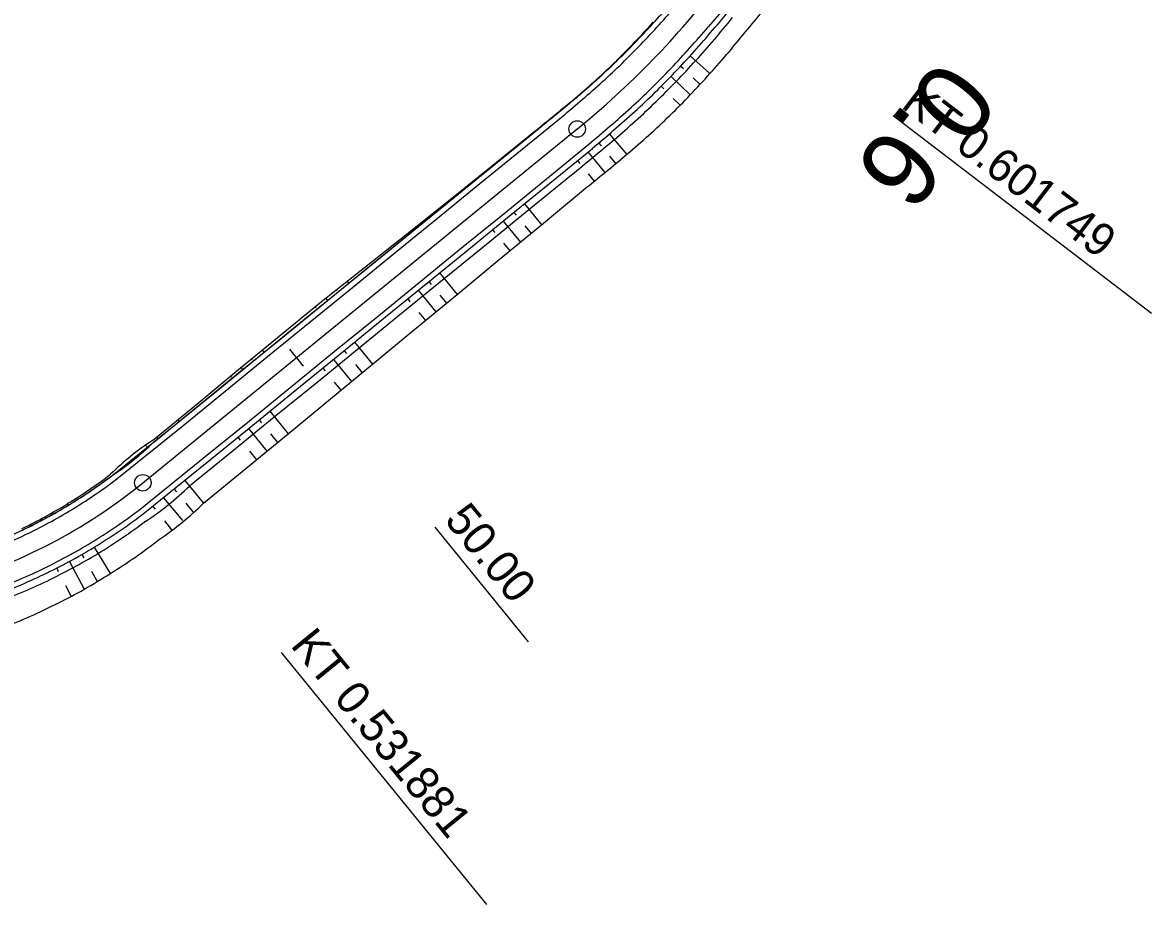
# Model space of a CAD drawing. Extents: x -481656 to -478728, y -1113199 to -1110710.
# Drawn here: x -479536.3 to -479433.2, y -1111452.2 to -1111371.6 of the extents above; entities that cross this region are included whole.
import ezdxf

# ---------------------------------------------------------------- set-up
doc = ezdxf.new("R2010")
doc.units = 0
for name, color, linetype in [('C5_HATCH_SLOPE_L', 7, 'Continuous'), ('C5_HATCH_SLOPE_R', 7, 'Continuous'), ('C5_HECTOMETRY', 7, 'Continuous'), ('C5_HLBODY', 7, 'Continuous'), ('C5_HRANA_TELESO', 7, 'Continuous'), ('C5_KORUNA', 7, 'Continuous'), ('C5_OSA', 7, 'Continuous'), ('C5_PRIKOP', 7, 'Continuous'), ('C5_STANICENI', 7, 'Continuous'), ('C5_ZPEVKRAJ', 7, 'Continuous')]:
    doc.layers.add(name, color=color, linetype=linetype)

msp = doc.modelspace()

# ---------------------------------------------------------------- linework, layer by layer
at = {"layer": 'C5_HATCH_SLOPE_L'}
for p, q in [((-479479.15, -1111372.09), (-479479.17, -1111372.07)), ((-479479.13, -1111372.11), (-479479.13, -1111372.11)), ((-479483.43, -1111376.4), (-479483.45, -1111376.38)), ((-479484.34, -1111377.2), (-479484.35, -1111377.19)), ((-479484.33, -1111377.22), (-479484.33, -1111377.22)), ((-479486.18, -1111378.79), (-479486.18, -1111378.78)), ((-479486.16, -1111378.81), (-479486.16, -1111378.81)), ((-479485.24, -1111378.02), (-479485.26, -1111378)), ((-479490.97, -1111382.75), (-479491, -1111382.71)), ((-479491.96, -1111383.51), (-479491.97, -1111383.5)), ((-479491.94, -1111383.54), (-479491.95, -1111383.53)), ((-479493.9, -1111385.09), (-479493.91, -1111385.08)), ((-479493.88, -1111385.12), (-479493.88, -1111385.11)), ((-479492.91, -1111384.33), (-479492.94, -1111384.29)), ((-479498.73, -1111389.06), (-479498.79, -1111388.98)), ((-479499.74, -1111389.8), (-479499.77, -1111389.76)), ((-479499.69, -1111389.85), (-479499.7, -1111389.85)), ((-479501.69, -1111391.37), (-479501.73, -1111391.31)), ((-479500.66, -1111390.64), (-479500.75, -1111390.53)), ((-479501.63, -1111391.43), (-479501.64, -1111391.43)), ((-479506.48, -1111395.38), (-479506.63, -1111395.19)), ((-479507.53, -1111396.07), (-479507.6, -1111395.98)), ((-479507.45, -1111396.17), (-479507.45, -1111396.17)), ((-479508.41, -1111396.96), (-479508.58, -1111396.76)), ((-479509.47, -1111397.64), (-479509.55, -1111397.54)), ((-479509.38, -1111397.75), (-479509.39, -1111397.75)), ((-479514.23, -1111401.7), (-479514.39, -1111401.5)), ((-479515.28, -1111402.39), (-479515.36, -1111402.29)), ((-479515.2, -1111402.49), (-479515.2, -1111402.49)), ((-479516.17, -1111403.28), (-479516.33, -1111403.08)), ((-479517.22, -1111403.97), (-479517.29, -1111403.88)), ((-479517.14, -1111404.07), (-479517.14, -1111404.06)), ((-479523.02, -1111408.72), (-479523.08, -1111408.65)), ((-479522.95, -1111408.81), (-479522.95, -1111408.8)), ((-479521.98, -1111408.02), (-479522.11, -1111407.85)), ((-479523.92, -1111409.6), (-479524.05, -1111409.44)), ((-479524.95, -1111410.3), (-479525.01, -1111410.23)), ((-479524.89, -1111410.39), (-479524.89, -1111410.38)), ((-479532.09, -1111415.68), (-479532.18, -1111415.53)), ((-479534.16, -1111416.87), (-479534.24, -1111416.72)), ((-479533.16, -1111416.21), (-479533.2, -1111416.14)), ((-479533.12, -1111416.28), (-479533.12, -1111416.28)), ((-479535.26, -1111417.35), (-479535.29, -1111417.28)), ((-479535.22, -1111417.42), (-479535.22, -1111417.42))]:
    msp.add_line(p, q, dxfattribs=at)
at = {"layer": 'C5_HATCH_SLOPE_R'}
for p, q in [((-479475.31, -1111374.61), (-479473.52, -1111376.24)), ((-479476.18, -1111375.55), (-479475.94, -1111375.78)), ((-479477.07, -1111376.48), (-479475.31, -1111378.18)), ((-479475.05, -1111376.61), (-479474.41, -1111377.22)), ((-479477.97, -1111377.4), (-479477.73, -1111377.63)), ((-479476.87, -1111378.5), (-479476.24, -1111379.13)), ((-479482.68, -1111381.77), (-479481.1, -1111383.62)), ((-479483.67, -1111382.59), (-479483.45, -1111382.85)), ((-479484.65, -1111383.4), (-479483.11, -1111385.28)), ((-479482.68, -1111383.79), (-479482.11, -1111384.47)), ((-479485.62, -1111384.19), (-479485.41, -1111384.45)), ((-479484.64, -1111385.39), (-479484.08, -1111386.07)), ((-479490.46, -1111388.14), (-479488.89, -1111390.07)), ((-479491.43, -1111388.93), (-479491.22, -1111389.18)), ((-479492.4, -1111389.72), (-479490.82, -1111391.65)), ((-479490.43, -1111390.15), (-479489.85, -1111390.86)), ((-479493.37, -1111390.51), (-479493.16, -1111390.76)), ((-479492.37, -1111391.73), (-479491.79, -1111392.44)), ((-479499.18, -1111395.24), (-479498.97, -1111395.5)), ((-479498.21, -1111394.45), (-479496.61, -1111396.42)), ((-479500.15, -1111396.03), (-479498.54, -1111398.01)), ((-479498.17, -1111396.49), (-479497.57, -1111397.22)), ((-479501.12, -1111396.82), (-479500.91, -1111397.08)), ((-479500.1, -1111398.07), (-479499.5, -1111398.81)), ((-479506.93, -1111401.56), (-479506.72, -1111401.82)), ((-479505.97, -1111400.77), (-479504.32, -1111402.79)), ((-479507.9, -1111402.35), (-479506.25, -1111404.38)), ((-479508.87, -1111403.14), (-479508.66, -1111403.4)), ((-479505.9, -1111402.83), (-479505.28, -1111403.58)), ((-479507.83, -1111404.42), (-479507.21, -1111405.18)), ((-479513.72, -1111407.09), (-479512.04, -1111409.15)), ((-479515.66, -1111408.67), (-479513.97, -1111410.74)), ((-479514.69, -1111407.88), (-479514.48, -1111408.14)), ((-479516.62, -1111409.46), (-479516.41, -1111409.72)), ((-479513.64, -1111409.17), (-479513, -1111409.94)), ((-479515.57, -1111410.75), (-479514.94, -1111411.53)), ((-479521.47, -1111413.41), (-479519.77, -1111415.5)), ((-479523.41, -1111414.99), (-479521.69, -1111417.09)), ((-479522.44, -1111414.2), (-479522.23, -1111414.45)), ((-479524.4, -1111415.79), (-479524.19, -1111416.05)), ((-479521.37, -1111415.5), (-479520.73, -1111416.29)), ((-479523.34, -1111417.12), (-479522.7, -1111417.93)), ((-479530.88, -1111420.19), (-479530.71, -1111420.48)), ((-479529.76, -1111419.52), (-479528.29, -1111421.93)), ((-479532.02, -1111420.82), (-479530.66, -1111423.34)), ((-479533.18, -1111421.43), (-479533.03, -1111421.73)), ((-479530.01, -1111421.71), (-479529.47, -1111422.65)), ((-479532.37, -1111423.02), (-479531.86, -1111424.01))]:
    msp.add_line(p, q, dxfattribs=at)
at = {"layer": 'C5_HLBODY'}
for p, q in [((-479456.77, -1111380.07), (-479433.19, -1111398.12)), ((-479512.67, -1111429.14), (-479493.91, -1111452.16))]:
    msp.add_line(p, q, dxfattribs=at)
for centre in [(-479485.64, -1111381.3), (-479525.31, -1111413.63)]:
    msp.add_circle(centre, 0.75, dxfattribs=at)
at = {"layer": 'C5_HRANA_TELESO'}
for p, q in [((-479493.34, -1111384.61), (-479489.46, -1111381.46)), ((-479497.23, -1111387.75), (-479493.34, -1111384.61)), ((-479488.89, -1111390.07), (-479485.05, -1111386.86)), ((-479501.15, -1111390.85), (-479497.23, -1111387.75)), ((-479492.76, -1111393.23), (-479488.89, -1111390.07)), ((-479505.07, -1111393.96), (-479501.15, -1111390.85)), ((-479496.61, -1111396.42), (-479492.76, -1111393.23)), ((-479508.99, -1111397.06), (-479505.07, -1111393.96)), ((-479500.47, -1111399.6), (-479496.61, -1111396.42)), ((-479512.85, -1111400.24), (-479508.99, -1111397.06)), ((-479516.72, -1111403.41), (-479512.85, -1111400.24)), ((-479504.32, -1111402.79), (-479500.47, -1111399.6)), ((-479520.57, -1111406.59), (-479516.72, -1111403.41)), ((-479508.18, -1111405.97), (-479504.32, -1111402.79)), ((-479524.44, -1111409.76), (-479520.57, -1111406.59)), ((-479512.04, -1111409.15), (-479508.18, -1111405.97)), ((-479515.9, -1111412.32), (-479512.04, -1111409.15)), ((-479519.77, -1111415.5), (-479515.9, -1111412.32))]:
    msp.add_line(p, q, dxfattribs=at)
for centre, radius, start, end in [((-479502, -1111344.39), 42.33, 318.9236, 325.8334), ((-479536.51, -1111319.63), 77.7, 314.5054, 318.0864), ((-479536.39, -1111319.54), 84.67, 317.9557, 321.5367), ((-479536.12, -1111319.24), 77.72, 310.5149, 314.0959), ((-479536.52, -1111319.65), 84.69, 314.4898, 318.0708), ((-479635.44, -1111199.68), 233.14, 308.769, 309.9841), ((-479535.95, -1111319.08), 84.7, 310.3672, 313.9482), ((-479644.14, -1111188.76), 254.07, 308.7674, 309.9206), ((-479511.47, -1111429.7), 23.78, 123.0473, 134.8927), ((-479557.03, -1111374.97), 47.57, 301.4916, 307.2212), ((-479557.01, -1111374.94), 47.59, 295.727, 301.4566), ((-479539.1, -1111395.94), 27.5, 303.8489, 314.6741), ((-479557.49, -1111375.29), 55.03, 302.0493, 307.7794), ((-479557.79, -1111375.37), 55.12, 296.6235, 302.354), ((-479557.96, -1111375.33), 55.23, 291.0412, 296.7721)]:
    msp.add_arc(centre, radius, start, end, dxfattribs=at)
at = {"layer": 'C5_KORUNA'}
for p, q in [((-479490.97, -1111382.75), (-479487.1, -1111379.59)), ((-479494.85, -1111385.91), (-479490.97, -1111382.75)), ((-479488.13, -1111386.24), (-479484.25, -1111383.08)), ((-479498.73, -1111389.06), (-479494.85, -1111385.91)), ((-479492.01, -1111389.39), (-479488.13, -1111386.24)), ((-479502.6, -1111392.22), (-479498.73, -1111389.06)), ((-479495.88, -1111392.55), (-479492.01, -1111389.39)), ((-479506.48, -1111395.38), (-479502.6, -1111392.22)), ((-479499.76, -1111395.71), (-479495.88, -1111392.55)), ((-479510.35, -1111398.54), (-479506.48, -1111395.38)), ((-479503.63, -1111398.87), (-479499.76, -1111395.71)), ((-479514.23, -1111401.7), (-479510.35, -1111398.54)), ((-479507.51, -1111402.03), (-479503.63, -1111398.87)), ((-479518.1, -1111404.86), (-479514.23, -1111401.7)), ((-479511.39, -1111405.19), (-479507.51, -1111402.03)), ((-479521.98, -1111408.02), (-479518.1, -1111404.86)), ((-479515.26, -1111408.35), (-479511.39, -1111405.19)), ((-479528.14, -1111413), (-479521.98, -1111408.02)), ((-479519.14, -1111411.51), (-479515.26, -1111408.35)), ((-479525.43, -1111416.59), (-479519.14, -1111411.51))]:
    msp.add_line(p, q, dxfattribs=at)
for centre, radius, start, end in [((-479503.84, -1111344.76), 41.12, 317.9996, 325.1159), ((-479536.18, -1111319.29), 77.75, 316.3068, 319.8878), ((-479536.18, -1111319.29), 82.25, 316.3068, 319.8878), ((-479536.18, -1111319.29), 77.75, 312.7258, 316.3068), ((-479638.08, -1111201.8), 233.25, 310.3381, 311.5319), ((-479536.18, -1111319.29), 82.25, 312.7259, 316.3068), ((-479643.98, -1111195), 246.75, 310.3394, 311.5326), ((-479556.9, -1111374.87), 47.75, 301.2953, 307.0249), ((-479556.9, -1111374.87), 47.75, 295.5657, 301.2953), ((-479556.9, -1111374.87), 52.25, 301.2953, 307.0249), ((-479556.9, -1111374.87), 47.75, 289.8361, 295.5657), ((-479556.9, -1111374.87), 52.25, 295.5657, 301.2953), ((-479556.9, -1111374.87), 52.25, 289.8361, 295.5657)]:
    msp.add_arc(centre, radius, start, end, dxfattribs=at)
at = {"layer": 'C5_OSA'}
msp.add_line((-479525.99, -1111414.19), (-479485.64, -1111381.3), dxfattribs=at)
for centre, radius, start, end in [((-479536.18, -1111319.29), 80, 309.1801, 322.5669), ((-479556.9, -1111374.87), 50, 285.9337, 309.1802)]:
    msp.add_arc(centre, radius, start, end, dxfattribs=at)
at = {"layer": 'C5_PRIKOP'}
for p, q in [((-479493.31, -1111384.64), (-479489.43, -1111381.48)), ((-479497.19, -1111387.8), (-479493.31, -1111384.64)), ((-479490.04, -1111388.65), (-479486.17, -1111385.49)), ((-479501.06, -1111390.96), (-479497.19, -1111387.8)), ((-479493.92, -1111391.81), (-479490.04, -1111388.65)), ((-479504.94, -1111394.12), (-479501.06, -1111390.96)), ((-479497.79, -1111394.97), (-479493.92, -1111391.81)), ((-479508.81, -1111397.27), (-479504.94, -1111394.12)), ((-479501.67, -1111398.13), (-479497.79, -1111394.97)), ((-479512.69, -1111400.43), (-479508.81, -1111397.27)), ((-479505.54, -1111401.29), (-479501.67, -1111398.13)), ((-479516.57, -1111403.59), (-479512.69, -1111400.43)), ((-479509.42, -1111404.45), (-479505.54, -1111401.29)), ((-479520.44, -1111406.75), (-479516.57, -1111403.59)), ((-479513.3, -1111407.6), (-479509.42, -1111404.45)), ((-479524.32, -1111409.91), (-479520.44, -1111406.75)), ((-479517.17, -1111410.76), (-479513.3, -1111407.6)), ((-479521.05, -1111413.92), (-479517.17, -1111410.76))]:
    msp.add_line(p, q, dxfattribs=at)
for centre, radius, start, end in [((-479536.18, -1111319.29), 77.74, 314.1525, 317.7335), ((-479536.18, -1111319.29), 82.92, 317.7335, 321.3145), ((-479536.18, -1111319.29), 77.74, 310.5715, 314.1525), ((-479536.18, -1111319.29), 82.92, 314.1525, 317.7335), ((-479635.69, -1111199.82), 233.22, 308.8383, 310.0532), ((-479536.18, -1111319.29), 82.92, 310.5715, 314.1525), ((-479642.28, -1111191.83), 248.75, 308.8724, 310.0404), ((-479541.11, -1111392.94), 23.87, 302.8775, 314.6953), ((-479556.9, -1111374.87), 47.74, 301.2953, 307.0249), ((-479539.53, -1111394.99), 26.46, 303.2195, 314.3012), ((-479556.9, -1111374.87), 47.74, 295.5657, 301.2953), ((-479556.9, -1111374.87), 52.92, 301.2953, 307.0249), ((-479556.9, -1111374.87), 52.92, 295.5657, 301.2953), ((-479556.9, -1111374.87), 52.92, 289.8361, 295.5657)]:
    msp.add_arc(centre, radius, start, end, dxfattribs=at)
at = {"layer": 'C5_STANICENI'}
for p, q in [((-479510.63, -1111402.96), (-479511.89, -1111401.41)), ((-479498.63, -1111417.69), (-479490.1, -1111428.15))]:
    msp.add_line(p, q, dxfattribs=at)
at = {"layer": 'C5_ZPEVKRAJ'}
for p, q in [((-479490.66, -1111383.14), (-479486.78, -1111379.98)), ((-479488.45, -1111385.85), (-479484.57, -1111382.69)), ((-479494.53, -1111386.29), (-479490.66, -1111383.14)), ((-479492.32, -1111389.01), (-479488.45, -1111385.85)), ((-479498.41, -1111389.45), (-479494.53, -1111386.29)), ((-479496.2, -1111392.17), (-479492.32, -1111389.01)), ((-479502.29, -1111392.61), (-479498.41, -1111389.45)), ((-479500.07, -1111395.32), (-479496.2, -1111392.17)), ((-479506.16, -1111395.77), (-479502.29, -1111392.61)), ((-479503.95, -1111398.48), (-479500.07, -1111395.32)), ((-479510.04, -1111398.93), (-479506.16, -1111395.77)), ((-479507.83, -1111401.64), (-479503.95, -1111398.48)), ((-479513.91, -1111402.09), (-479510.04, -1111398.93)), ((-479511.7, -1111404.8), (-479507.83, -1111401.64)), ((-479517.79, -1111405.25), (-479513.91, -1111402.09)), ((-479521.66, -1111408.41), (-479517.79, -1111405.25)), ((-479515.58, -1111407.96), (-479511.7, -1111404.8)), ((-479527.84, -1111413.4), (-479521.66, -1111408.41)), ((-479519.45, -1111411.12), (-479515.58, -1111407.96)), ((-479525.73, -1111416.19), (-479519.45, -1111411.12))]:
    msp.add_line(p, q, dxfattribs=at)
for centre, radius, start, end in [((-479504.03, -1111344.61), 40.88, 317.9957, 325.1228), ((-479536.18, -1111319.29), 78.25, 316.3068, 319.8878), ((-479536.18, -1111319.29), 81.75, 316.3068, 319.8878), ((-479536.18, -1111319.29), 78.25, 312.7258, 316.3068), ((-479536.18, -1111319.29), 81.75, 312.7259, 316.3068), ((-479638.73, -1111201.04), 234.75, 310.3383, 311.532), ((-479643.32, -1111195.75), 245.25, 310.3393, 311.5325), ((-479556.9, -1111374.87), 48.25, 301.2953, 307.0249), ((-479556.9, -1111374.87), 48.25, 295.5657, 301.2953), ((-479556.9, -1111374.87), 51.75, 301.2953, 307.0249), ((-479556.9, -1111374.87), 48.25, 289.8361, 295.5657), ((-479556.9, -1111374.87), 51.75, 295.5657, 301.2953), ((-479556.9, -1111374.87), 51.75, 289.8361, 295.5657)]:
    msp.add_arc(centre, radius, start, end, dxfattribs=at)

# ---------------------------------------------------------------- texts
at = {"layer": 'C5_HECTOMETRY'}
msp.add_text('0.6', height=6.999, rotation=231.2688, dxfattribs=at).set_placement((-479452.36, -1111374.61))
at = {"layer": 'C5_HLBODY'}
for s, height, rotation, p in [('KT 0.601749', 2.999, 322.5669, (-479456.17, -1111379.28)), ('KT 0.531881', 3, 309.1802, (-479511.9, -1111428.5))]:
    msp.add_text(s, height=height, rotation=rotation, dxfattribs=at).set_placement(p)
at = {"layer": 'C5_STANICENI'}
msp.add_text('50.00', height=3, rotation=309.1802, dxfattribs=at).set_placement((-479497.85, -1111417.06))

doc.saveas('drawing.dxf')
